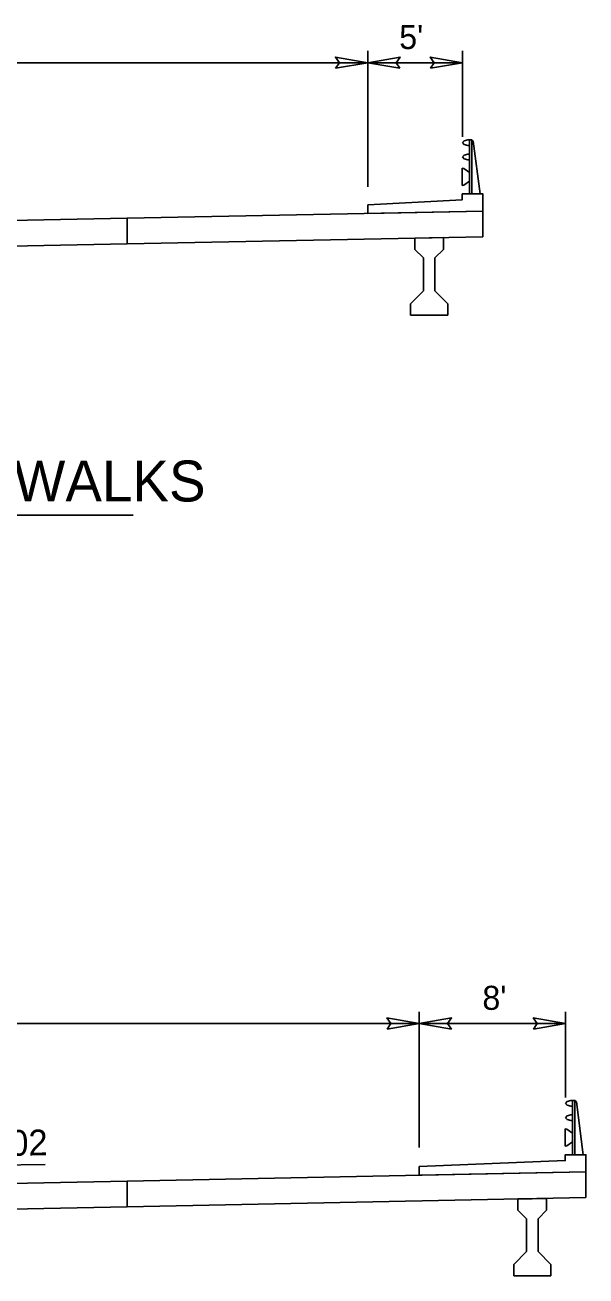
# Model space of a CAD drawing. Extents: x 1640342 to 1730599, y 538663 to 843747.
# Drawn here: x 1730338.3 to 1730371, y 539267.6 to 539340.5 of the extents above; entities that cross this region are included whole.
import ezdxf

# ---------------------------------------------------------------- set-up
doc = ezdxf.new("R2010")
doc.units = 0
for name, color, linetype in [('Default', 7, 'Continuous'), ('Typical Pavement Slope CELL', 7, 'Continuous'), ('Typical Pavement Slope Information CELL', 7, 'Continuous'), ('Typical Shoulder Slope CELL', 7, 'Continuous'), ('Typical Text Label CELL', 7, 'Continuous')]:
    doc.layers.add(name, color=color, linetype=linetype)

msp = doc.modelspace()

# ---------------------------------------------------------------- linework, layer by layer
at = {"layer": 'Default'}
for p, q in [((1730358.263, 539331.076), (1730358.263, 539338.988)), ((1730363.781, 539333.983), (1730363.781, 539338.988)), ((1730358.263, 539338.295), (1730310.263, 539338.295)), ((1730363.781, 539338.295), (1730358.263, 539338.295)), ((1730361.259, 539275.117), (1730361.259, 539283.029)), ((1730369.778, 539278.024), (1730369.778, 539283.029)), ((1730361.259, 539282.336), (1730313.259, 539282.336)), ((1730369.778, 539282.336), (1730361.259, 539282.336))]:
    msp.add_line(p, q, dxfattribs=at)
for points in [[(1730356.388, 539337.973), (1730358.263, 539338.295), (1730356.378, 539338.629), (1730356.618, 539338.295)], [(1730360.137, 539337.973), (1730358.263, 539338.295), (1730360.147, 539338.629), (1730359.908, 539338.295)], [(1730361.907, 539337.973), (1730363.781, 539338.295), (1730361.897, 539338.629), (1730362.136, 539338.295)], [(1730359.385, 539282.013), (1730361.259, 539282.336), (1730359.375, 539282.669), (1730359.614, 539282.336)], [(1730363.134, 539282.013), (1730361.259, 539282.336), (1730363.144, 539282.669), (1730362.905, 539282.336)], [(1730367.904, 539282.013), (1730369.778, 539282.336), (1730367.893, 539282.669), (1730368.133, 539282.336)]]:
    msp.add_lwpolyline(points, close=True, dxfattribs=at)
for points in [[(1730361.009, 539328.079), (1730361.843, 539328.096), (1730362.676, 539328.112)], [(1730367.006, 539272.12), (1730367.84, 539272.136), (1730368.673, 539272.153)]]:
    msp.add_lwpolyline(points, dxfattribs=at)
at = {"layer": 'Typical Pavement Slope CELL'}
for p, q in [((1730344.259, 539329.244), (1730344.259, 539327.744)), ((1730344.256, 539273.165), (1730344.256, 539271.665))]:
    msp.add_line(p, q, dxfattribs=at)
for points in [[(1730364.178, 539333.814), (1730364.095, 539333.814), (1730363.866, 539333.752), (1730363.782, 539333.648)], [(1730363.782, 539333.648), (1730363.866, 539333.543), (1730364.095, 539333.481), (1730364.178, 539333.481)], [(1730364.178, 539330.658), (1730364.178, 539333.814)], [(1730364.178, 539333.814), (1730364.324, 539333.814)], [(1730364.178, 539333.648), (1730364.178, 539333.814)], [(1730364.178, 539333.481), (1730364.178, 539333.648)], [(1730364.324, 539333.814), (1730364.324, 539330.658)], [(1730364.324, 539333.814), (1730364.407, 539333.731), (1730364.803, 539330.658)], [(1730364.178, 539332.981), (1730364.095, 539332.981), (1730363.866, 539332.918), (1730363.782, 539332.814)], [(1730363.782, 539332.814), (1730363.866, 539332.71), (1730364.095, 539332.648), (1730364.178, 539332.648)], [(1730364.178, 539332.814), (1730364.178, 539332.981)], [(1730364.178, 539332.648), (1730364.178, 539332.814)], [(1730364.178, 539331.908), (1730363.85, 539332.148), (1730363.761, 539332.158)], [(1730363.761, 539332.158), (1730363.761, 539331.158)], [(1730364.178, 539331.658), (1730364.178, 539331.908)], [(1730364.178, 539331.408), (1730364.178, 539331.658)], [(1730363.761, 539331.158), (1730363.85, 539331.168), (1730364.178, 539331.408)], [(1730364.968, 539329.658), (1730344.259, 539329.244)], [(1730364.968, 539329.658), (1730364.968, 539328.158)], [(1730344.259, 539329.244), (1730282.263, 539328.004), (1730273.554, 539327.83)], [(1730344.259, 539327.744), (1730364.968, 539328.158)], [(1730361.009, 539327.429), (1730361.009, 539328.079)], [(1730362.676, 539328.112), (1730362.676, 539327.429)], [(1730273.554, 539326.33), (1730344.259, 539327.744)], [(1730361.509, 539326.929), (1730361.009, 539327.429)], [(1730362.676, 539327.429), (1730362.176, 539326.929)], [(1730361.509, 539325.012), (1730361.509, 539326.929)], [(1730362.176, 539326.929), (1730362.176, 539325.012)], [(1730360.759, 539324.262), (1730361.509, 539325.012)], [(1730362.176, 539325.012), (1730362.926, 539324.262)], [(1730360.759, 539323.596), (1730360.759, 539324.262)], [(1730362.926, 539324.262), (1730362.926, 539323.596)], [(1730362.926, 539323.596), (1730361.843, 539323.596), (1730360.759, 539323.596)], [(1730370.175, 539277.855), (1730370.092, 539277.855), (1730369.862, 539277.793), (1730369.779, 539277.688)], [(1730370.175, 539274.699), (1730370.175, 539277.855)], [(1730370.175, 539277.855), (1730370.321, 539277.855)], [(1730370.175, 539277.688), (1730370.175, 539277.855)], [(1730370.321, 539277.855), (1730370.321, 539274.699)], [(1730370.321, 539277.855), (1730370.404, 539277.772), (1730370.8, 539274.699)], [(1730369.779, 539277.688), (1730369.862, 539277.584), (1730370.092, 539277.522), (1730370.175, 539277.522)], [(1730370.175, 539277.022), (1730370.092, 539277.022), (1730369.862, 539276.959), (1730369.779, 539276.855)], [(1730370.175, 539277.522), (1730370.175, 539277.688)], [(1730370.175, 539276.855), (1730370.175, 539277.022)], [(1730369.779, 539276.855), (1730369.862, 539276.751), (1730370.092, 539276.688), (1730370.175, 539276.688)], [(1730370.175, 539276.688), (1730370.175, 539276.855)], [(1730370.175, 539275.949), (1730369.847, 539276.188), (1730369.758, 539276.199)], [(1730369.758, 539276.199), (1730369.758, 539275.199)], [(1730370.175, 539275.699), (1730370.175, 539275.949)], [(1730370.175, 539275.449), (1730370.175, 539275.699)], [(1730369.758, 539275.199), (1730369.847, 539275.209), (1730370.175, 539275.449)], [(1730370.965, 539273.699), (1730344.256, 539273.165)], [(1730370.965, 539273.699), (1730370.965, 539272.199)], [(1730344.256, 539273.165), (1730282.263, 539271.925), (1730273.554, 539271.751)], [(1730344.256, 539271.665), (1730370.965, 539272.199)], [(1730367.006, 539271.47), (1730367.006, 539272.12)], [(1730368.673, 539272.153), (1730368.673, 539271.47)], [(1730273.554, 539270.251), (1730344.256, 539271.665)], [(1730367.506, 539270.97), (1730367.006, 539271.47)], [(1730368.673, 539271.47), (1730368.173, 539270.97)], [(1730367.506, 539269.053), (1730367.506, 539270.97)], [(1730368.173, 539270.97), (1730368.173, 539269.053)], [(1730366.756, 539268.303), (1730367.506, 539269.053)], [(1730368.173, 539269.053), (1730368.923, 539268.303)], [(1730366.756, 539267.636), (1730366.756, 539268.303)], [(1730368.923, 539268.303), (1730368.923, 539267.636)], [(1730368.923, 539267.636), (1730367.84, 539267.636), (1730366.756, 539267.636)]]:
    msp.add_lwpolyline(points, dxfattribs=at)
at = {"layer": 'Typical Pavement Slope Information CELL'}
msp.add_line((1730334.818, 539274.044), (1730339.477, 539274.137), dxfattribs=at)
at = {"layer": 'Typical Shoulder Slope CELL'}
for p, q in [((1730358.259, 539330.024), (1730358.259, 539329.524)), ((1730361.259, 539274.005), (1730361.259, 539273.505))]:
    msp.add_line(p, q, dxfattribs=at)
for points in [[(1730358.259, 539330.024), (1730363.76, 539330.314), (1730363.761, 539330.658), (1730364.968, 539330.658), (1730364.968, 539329.658)], [(1730364.968, 539329.658), (1730358.259, 539329.524)], [(1730361.259, 539274.005), (1730369.757, 539274.355), (1730369.758, 539274.699), (1730370.965, 539274.699), (1730370.965, 539273.699)], [(1730370.965, 539273.699), (1730361.259, 539273.505)]]:
    msp.add_lwpolyline(points, dxfattribs=at)
at = {"layer": 'Typical Text Label CELL'}
msp.add_line((1730293.933, 539311.944), (1730344.602, 539311.944), dxfattribs=at)

# ---------------------------------------------------------------- texts
at = {"layer": 'Default'}
for s, p in [("5'", (1730360.093, 539339.095)), ("8'", (1730364.935, 539283.136))]:
    msp.add_text(s, height=1.4, dxfattribs=at).set_placement(p)
msp.add_text('0.02', height=1.5, rotation=1.14576, dxfattribs=at).set_placement((1730335.737, 539274.594))
at = {"layer": 'Typical Text Label CELL'}
msp.add_text("BRIDGE TYPICAL W/  5' SIDEWALKS", height=2.38712, rotation=360, dxfattribs=at).set_placement((1730293.933, 539312.744))

doc.saveas('drawing.dxf')
